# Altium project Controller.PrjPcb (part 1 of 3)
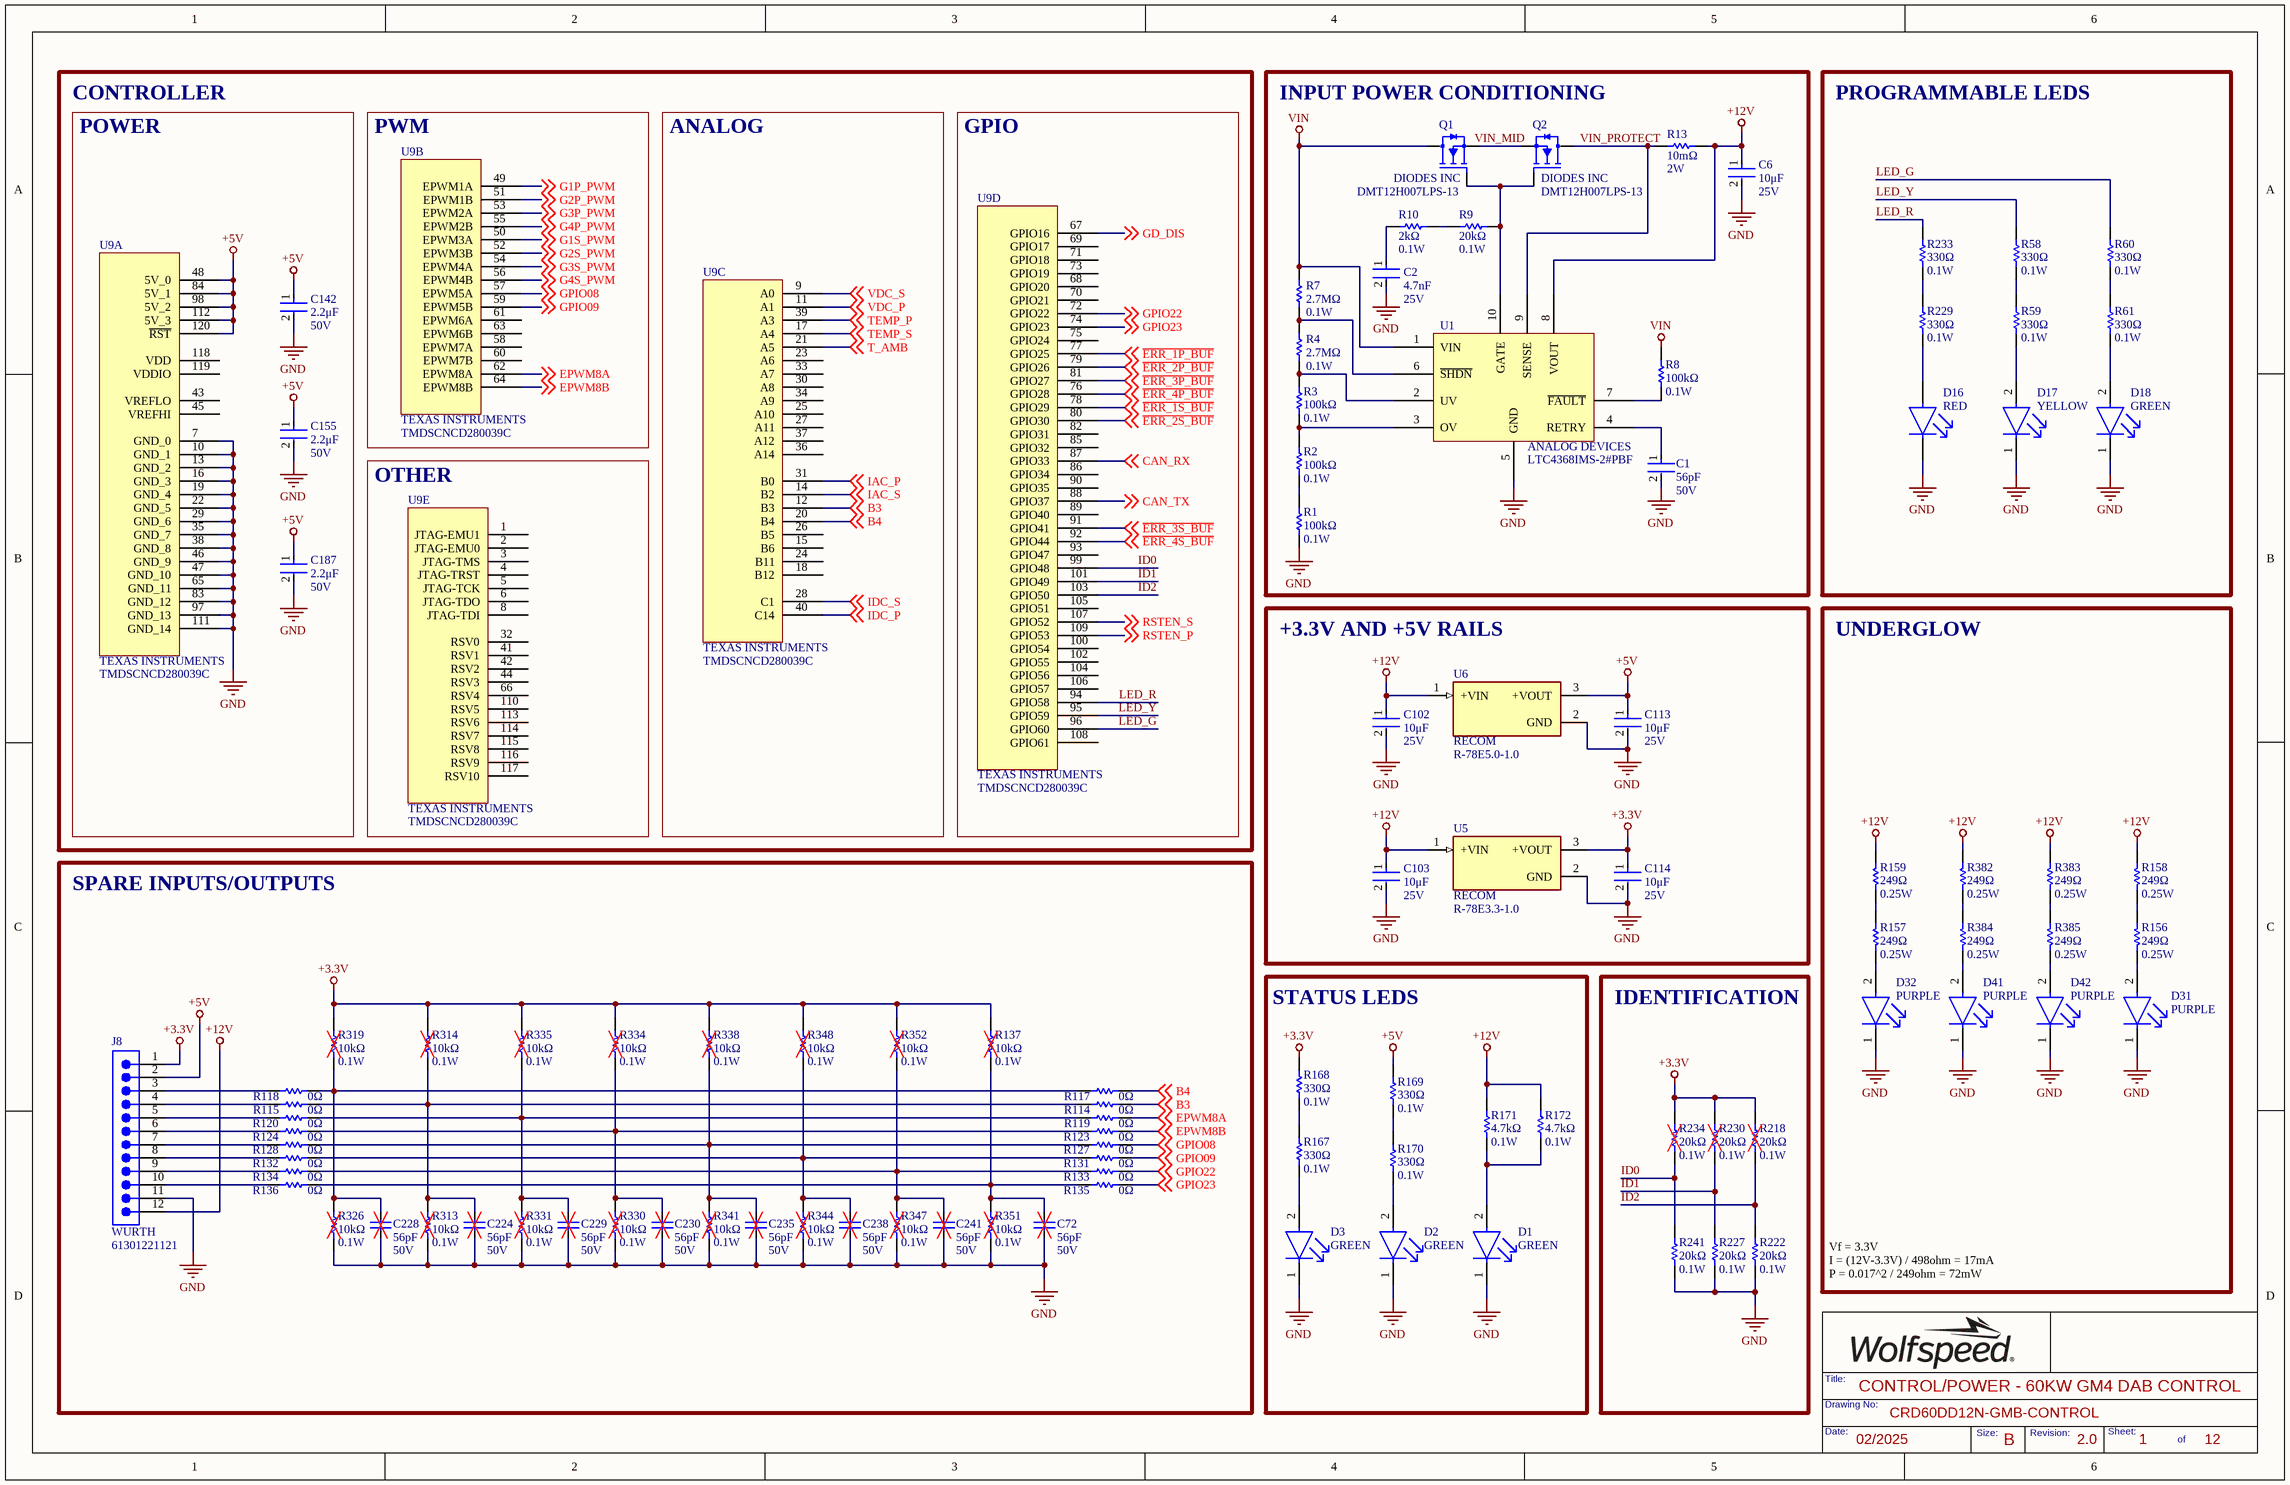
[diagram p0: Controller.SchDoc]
12 sheets, 761 parts. Net scope: global (net labels, ports and power ports of the same name join across sheets).
Board file: Controller.PcbDoc
Sheets:
  Controller.SchDoc
  Input-Output.SchDoc
  Drivers - 12P.SchDoc
  Drivers - 34P.SchDoc
  Drivers - 12S.SchDoc
  Drivers - 34S.SchDoc
  Fault Logic - P.SchDoc
  Fault Logic - S.SchDoc
  Level Shifting.SchDoc
  Voltage Sense.SchDoc
  Current Sense - P.SchDoc
  Current Sense - S.SchDoc

## Sheet Controller.SchDoc: CONTROL/POWER - 60KW GM4 DAB CONTROL
size 431 x 279 mm; Date: 02/2025; DocumentNumber: CRD60DD12N-GMB-CONTROL; Revision: 2.0; SheetNumber: 1; SheetTotal: 12; SheetSize: B

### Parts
C1  Capacitance: 56pF  Voltage Rating: 50V  [FP-C0603C-CF-IPC_B]  (hidden comment: CL10C560JB8NNNC)
C2  Voltage Rating: 25V  Capacitance: 4.7nF  [FP-C0603C-CF-IPC_B]  (hidden comment: C0603C472K3RAC7867)
C6  Voltage Rating: 25V  Capacitance: 10μF  [FP-CL31-IPC_B]  (hidden comment: CL31B106KAHSFNE)
C72  Capacitance: 56pF  Voltage Rating: 50V  [FP-C0603C-CF-IPC_B]  (hidden comment: CL10C560JB8NNNC)
C102  Voltage Rating: 25V  Capacitance: 10μF  [FP-CL31-IPC_B]  (hidden comment: CL31B106KAHSFNE)
C103  Voltage Rating: 25V  Capacitance: 10μF  [FP-CL31-IPC_B]  (hidden comment: CL31B106KAHSFNE)
C113  Voltage Rating: 25V  Capacitance: 10μF  [FP-CL31-IPC_B]  (hidden comment: CL31B106KAHSFNE)
C114  Voltage Rating: 25V  Capacitance: 10μF  [FP-CL31-IPC_B]  (hidden comment: CL31B106KAHSFNE)
C142  Voltage Rating: 50V  Capacitance: 2.2μF  [FP-C0603C-CF-IPC_B]  (hidden comment: GRT188R61H225ME13D)
C155  Voltage Rating: 50V  Capacitance: 2.2μF  [FP-C0603C-CF-IPC_B]  (hidden comment: GRT188R61H225ME13D)
C187  Voltage Rating: 50V  Capacitance: 2.2μF  [FP-C0603C-CF-IPC_B]  (hidden comment: GRT188R61H225ME13D)
C224  Capacitance: 56pF  Voltage Rating: 50V  [FP-C0603C-CF-IPC_B]  (hidden comment: CL10C560JB8NNNC)
C228  Capacitance: 56pF  Voltage Rating: 50V  [FP-C0603C-CF-IPC_B]  (hidden comment: CL10C560JB8NNNC)
C229  Capacitance: 56pF  Voltage Rating: 50V  [FP-C0603C-CF-IPC_B]  (hidden comment: CL10C560JB8NNNC)
C230  Capacitance: 56pF  Voltage Rating: 50V  [FP-C0603C-CF-IPC_B]  (hidden comment: CL10C560JB8NNNC)
C235  Capacitance: 56pF  Voltage Rating: 50V  [FP-C0603C-CF-IPC_B]  (hidden comment: CL10C560JB8NNNC)
C238  Capacitance: 56pF  Voltage Rating: 50V  [FP-C0603C-CF-IPC_B]  (hidden comment: CL10C560JB8NNNC)
C241  Capacitance: 56pF  Voltage Rating: 50V  [FP-C0603C-CF-IPC_B]  (hidden comment: CL10C560JB8NNNC)
D1  value GREEN  [FP-LTST-C171GKT-MFG]  (hidden comment: LTST-C171GKT)
D2  value GREEN  [FP-LTST-C171GKT-MFG]  (hidden comment: LTST-C171GKT)
D3  value GREEN  [FP-LTST-C171GKT-MFG]  (hidden comment: LTST-C171GKT)
D16  value RED  [FP-LTST-C171GKT-MFG-RED]  (hidden comment: HSMC-C170)
D17  value YELLOW  [FP-LTST-C171GKT-MFG-YELLOW]  (hidden comment: LTST-C171KSKT)
D18  value GREEN  [FP-LTST-C171GKT-MFG]  (hidden comment: LTST-C171GKT)
D31  Color: PURPLE  [FP-APTR3216SECK-MFG]  (hidden comment: APTR3216-VFX)
D32  Color: PURPLE  [FP-APTR3216SECK-MFG]  (hidden comment: APTR3216-VFX)
D41  Color: PURPLE  [FP-APTR3216SECK-MFG]  (hidden comment: APTR3216-VFX)
D42  Color: PURPLE  [FP-APTR3216SECK-MFG]  (hidden comment: APTR3216-VFX)
J8  Manufacturer Print: WURTH  [FP-61301221121-MFG]  (hidden comment: 61301221121)
Q1  DMT12H007LPS-13  Manufacturer: DIODES INC  [FP-PowerDI5060-8-MFG]
Q2  DMT12H007LPS-13  Manufacturer: DIODES INC  [FP-PowerDI5060-8-MFG]
R1  Resistance: 100kΩ  Power Rating: 0.1W  [FP-MCR03-IPC_B]  (hidden comment: RC0603FR-07100KL)
R2  Resistance: 100kΩ  Power Rating: 0.1W  [FP-MCR03-IPC_B]  (hidden comment: RC0603FR-07100KL)
R3  Resistance: 100kΩ  Power Rating: 0.1W  [FP-MCR03-IPC_B]  (hidden comment: RC0603FR-07100KL)
R4  Power Rating: 0.1W  Resistance: 2.7MΩ  [FP-MCR03-IPC_B]  (hidden comment: RC0603JR-072M7L)
R7  Power Rating: 0.1W  Resistance: 2.7MΩ  [FP-MCR03-IPC_B]  (hidden comment: RC0603JR-072M7L)
R8  Resistance: 100kΩ  Power Rating: 0.1W  [FP-MCR03-IPC_B]  (hidden comment: RC0603FR-07100KL)
R9  Resistance: 20kΩ  Power Rating: 0.1W  [FP-MCR03-IPC_B]  (hidden comment: CRCW060320K0FKTA)
R10  Resistance: 2kΩ  Power Rating: 0.1W  [FP-MCR03-IPC_B]  (hidden comment: RT0603DRE072KL)
R13  Resistance: 10mΩ  Max Power Dissipation: 2W  [FP-RL2512-IPC_A]  (hidden comment: PE2512FKE7W0R01L)
R58  Resistance: 330Ω  Power Rating: 0.1W  [FP-MCR03-IPC_B]  (hidden comment: RC0603FR-13330RL)
R59  Resistance: 330Ω  Power Rating: 0.1W  [FP-MCR03-IPC_B]  (hidden comment: RC0603FR-13330RL)
R60  Resistance: 330Ω  Power Rating: 0.1W  [FP-MCR03-IPC_B]  (hidden comment: RC0603FR-13330RL)
R61  Resistance: 330Ω  Power Rating: 0.1W  [FP-MCR03-IPC_B]  (hidden comment: RC0603FR-13330RL)
R114  Resistance: 0Ω  [FP-MCR03-IPC_B]  (hidden comment: CRCW06030000Z0EB)
R115  Resistance: 0Ω  [FP-MCR03-IPC_B]  (hidden comment: CRCW06030000Z0EB)
R117  Resistance: 0Ω  [FP-MCR03-IPC_B]  (hidden comment: CRCW06030000Z0EB)
R118  Resistance: 0Ω  [FP-MCR03-IPC_B]  (hidden comment: CRCW06030000Z0EB)
R119  Resistance: 0Ω  [FP-MCR03-IPC_B]  (hidden comment: CRCW06030000Z0EB)
R120  Resistance: 0Ω  [FP-MCR03-IPC_B]  (hidden comment: CRCW06030000Z0EB)
R123  Resistance: 0Ω  [FP-MCR03-IPC_B]  (hidden comment: CRCW06030000Z0EB)
R124  Resistance: 0Ω  [FP-MCR03-IPC_B]  (hidden comment: CRCW06030000Z0EB)
R127  Resistance: 0Ω  [FP-MCR03-IPC_B]  (hidden comment: CRCW06030000Z0EB)
R128  Resistance: 0Ω  [FP-MCR03-IPC_B]  (hidden comment: CRCW06030000Z0EB)
R131  Resistance: 0Ω  [FP-MCR03-IPC_B]  (hidden comment: CRCW06030000Z0EB)
R132  Resistance: 0Ω  [FP-MCR03-IPC_B]  (hidden comment: CRCW06030000Z0EB)
R133  Resistance: 0Ω  [FP-MCR03-IPC_B]  (hidden comment: CRCW06030000Z0EB)
R134  Resistance: 0Ω  [FP-MCR03-IPC_B]  (hidden comment: CRCW06030000Z0EB)
R135  Resistance: 0Ω  [FP-MCR03-IPC_B]  (hidden comment: CRCW06030000Z0EB)
R136  Resistance: 0Ω  [FP-MCR03-IPC_B]  (hidden comment: CRCW06030000Z0EB)
R137  Resistance: 10kΩ  Max Power Dissipation: 0.1W  [FP-MCR03-IPC_B]  (hidden comment: ERJ3EKF1002V)
R156  Resistance: 249Ω  Power Rating: 0.25W  [FP-MCR18-IPC_A]  (hidden comment: RC1206FR-07249RL)
R157  Resistance: 249Ω  Power Rating: 0.25W  [FP-MCR18-IPC_A]  (hidden comment: RC1206FR-07249RL)
R158  Resistance: 249Ω  Power Rating: 0.25W  [FP-MCR18-IPC_A]  (hidden comment: RC1206FR-07249RL)
R159  Resistance: 249Ω  Power Rating: 0.25W  [FP-MCR18-IPC_A]  (hidden comment: RC1206FR-07249RL)
R167  Resistance: 330Ω  Power Rating: 0.1W  [FP-MCR03-IPC_B]  (hidden comment: RC0603FR-13330RL)
R168  Resistance: 330Ω  Power Rating: 0.1W  [FP-MCR03-IPC_B]  (hidden comment: RC0603FR-13330RL)
R169  Resistance: 330Ω  Power Rating: 0.1W  [FP-MCR03-IPC_B]  (hidden comment: RC0603FR-13330RL)
R170  Resistance: 330Ω  Power Rating: 0.1W  [FP-MCR03-IPC_B]  (hidden comment: RC0603FR-13330RL)
R171  Resistance: 4.7kΩ  Power Rating: 0.1W  [FP-MCR03-IPC_B]  (hidden comment: CRCW06034K70FKTA)
R172  Resistance: 4.7kΩ  Power Rating: 0.1W  [FP-MCR03-IPC_B]  (hidden comment: CRCW06034K70FKTA)
R218  Resistance: 20kΩ  Power Rating: 0.1W  [FP-MCR03-IPC_B]  (hidden comment: CRCW060320K0FKTA)
R222  Resistance: 20kΩ  Power Rating: 0.1W  [FP-MCR03-IPC_B]  (hidden comment: CRCW060320K0FKTA)
R227  Resistance: 20kΩ  Power Rating: 0.1W  [FP-MCR03-IPC_B]  (hidden comment: CRCW060320K0FKTA)
R229  Resistance: 330Ω  Power Rating: 0.1W  [FP-MCR03-IPC_B]  (hidden comment: RC0603FR-13330RL)
R230  Resistance: 20kΩ  Power Rating: 0.1W  [FP-MCR03-IPC_B]  (hidden comment: CRCW060320K0FKTA)
R233  Resistance: 330Ω  Power Rating: 0.1W  [FP-MCR03-IPC_B]  (hidden comment: RC0603FR-13330RL)
R234  Resistance: 20kΩ  Power Rating: 0.1W  [FP-MCR03-IPC_B]  (hidden comment: CRCW060320K0FKTA)
R241  Resistance: 20kΩ  Power Rating: 0.1W  [FP-MCR03-IPC_B]  (hidden comment: CRCW060320K0FKTA)
R313  Resistance: 10kΩ  Max Power Dissipation: 0.1W  [FP-MCR03-IPC_B]  (hidden comment: ERJ3EKF1002V)
R314  Resistance: 10kΩ  Max Power Dissipation: 0.1W  [FP-MCR03-IPC_B]  (hidden comment: ERJ3EKF1002V)
R319  Resistance: 10kΩ  Max Power Dissipation: 0.1W  [FP-MCR03-IPC_B]  (hidden comment: ERJ3EKF1002V)
R326  Resistance: 10kΩ  Max Power Dissipation: 0.1W  [FP-MCR03-IPC_B]  (hidden comment: ERJ3EKF1002V)
R330  Resistance: 10kΩ  Max Power Dissipation: 0.1W  [FP-MCR03-IPC_B]  (hidden comment: ERJ3EKF1002V)
R331  Resistance: 10kΩ  Max Power Dissipation: 0.1W  [FP-MCR03-IPC_B]  (hidden comment: ERJ3EKF1002V)
R334  Resistance: 10kΩ  Max Power Dissipation: 0.1W  [FP-MCR03-IPC_B]  (hidden comment: ERJ3EKF1002V)
R335  Resistance: 10kΩ  Max Power Dissipation: 0.1W  [FP-MCR03-IPC_B]  (hidden comment: ERJ3EKF1002V)
R338  Resistance: 10kΩ  Max Power Dissipation: 0.1W  [FP-MCR03-IPC_B]  (hidden comment: ERJ3EKF1002V)
R341  Resistance: 10kΩ  Max Power Dissipation: 0.1W  [FP-MCR03-IPC_B]  (hidden comment: ERJ3EKF1002V)
R344  Resistance: 10kΩ  Max Power Dissipation: 0.1W  [FP-MCR03-IPC_B]  (hidden comment: ERJ3EKF1002V)
R347  Resistance: 10kΩ  Max Power Dissipation: 0.1W  [FP-MCR03-IPC_B]  (hidden comment: ERJ3EKF1002V)
R348  Resistance: 10kΩ  Max Power Dissipation: 0.1W  [FP-MCR03-IPC_B]  (hidden comment: ERJ3EKF1002V)
R351  Resistance: 10kΩ  Max Power Dissipation: 0.1W  [FP-MCR03-IPC_B]  (hidden comment: ERJ3EKF1002V)
R352  Resistance: 10kΩ  Max Power Dissipation: 0.1W  [FP-MCR03-IPC_B]  (hidden comment: ERJ3EKF1002V)
R382  Resistance: 249Ω  Power Rating: 0.25W  [FP-MCR18-IPC_A]  (hidden comment: RC1206FR-07249RL)
R383  Resistance: 249Ω  Power Rating: 0.25W  [FP-MCR18-IPC_A]  (hidden comment: RC1206FR-07249RL)
R384  Resistance: 249Ω  Power Rating: 0.25W  [FP-MCR18-IPC_A]  (hidden comment: RC1206FR-07249RL)
R385  Resistance: 249Ω  Power Rating: 0.25W  [FP-MCR18-IPC_A]  (hidden comment: RC1206FR-07249RL)
U1  LTC4368IMS-2#PBF  Manufacturer: ANALOG DEVICES  [SOP50P490X110-10N]
U5  R-78E3.3-1.0  Manufacturer Print: RECOM  [CONV_R-78E3.3-1.0]
U6  R-78E5.0-1.0  Manufacturer Print: RECOM  [CONV_R-78E5.0-1.0]
U9  Manufacturer: TEXAS INSTRUMENTS  [TMDSCNCD280039C_HORZ]  (hidden comment: TMDSCNCD280039C)  (parts A,B,C,D,E of 5)

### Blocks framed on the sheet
PWM: U9
ANALOG: U9
GPIO: U9
INPUT POWER CONDITIONING: C1 C2 C6 Q1 Q2 R1-R4 R7-R10 R13 U1
PROGRAMMABLE LEDS: D16-D18 R58-R61 R229 R233
OTHER: U9
+3.3V AND +5V RAILS: C102 C103 C113 C114 U5 U6
UNDERGLOW: D31 D32 D41 D42 R156-R159 R382-R385
SPARE INPUTS/OUTPUTS: C72 C224 C228-C230 C235 C238 C241 J8 R114 R115 R117-R120 R123 R124 R127 R128 R131-R137 R313 R314 R319 R326 R330 R331 R334 R335 R338 R341 R344 R347 R348 R351 R352
STATUS LEDS: D1-D3 R167-R172
IDENTIFICATION: R218 R222 R227 R230 R234 R241

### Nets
+3.3V: C114.1 J8.1 R137.2 R168.2 R218.2 R230.2 R234.2 R314.2 R319.2 R334.2 R335.2 R338.2 R348.2 R352.2 U5.3(+VOUT)
+5V: C113.1 C142.1 C155.1 C187.1 J8.2 R169.2 U6.3(+VOUT) U9.48(5V_0) U9.84(5V_1) U9.98(5V_2) U9.112(5V_3) U9.120(~{RST})
+12V: C6.1 C102.1 C103.1 J8.12 R13.2 R158.1 R159.1 R171.2 R172.2 R382.1 R383.1 U1.8(VOUT) U5.1(+VIN) U6.1(+VIN)
GND: C1.2 C2.2 C6.2 C72.2 C102.2 C103.2 C113.2 C114.2 C142.2 C155.2 C187.2 C224.2 C228.2 C229.2 C230.2 C235.2 C238.2 C241.2 D1.1(C) D2.1(C) D3.1(C) D16.1(C) D17.1(C) D18.1(C) D31.1(C) D32.1(C) D41.1(C) D42.1(C) J8.11 R1.1 R222.1 R227.1 R241.1 R313.1 R326.1 R330.1 R331.1 R341.1 R344.1 R347.1 R351.1 U1.5(GND) U5.2(GND) U6.2(GND) U9.7(GND_0) U9.10(GND_1) U9.13(GND_2) U9.16(GND_3) U9.19(GND_4) U9.22(GND_5) U9.29(GND_6) U9.35(GND_7) U9.38(GND_8) U9.46(GND_9) U9.47(GND_10) U9.65(GND_11) U9.83(GND_12) U9.97(GND_13) U9.111(GND_14)
VIN: Q1.5(D) R7.2 R8.2 U1.1(VIN)
B3: R114.2 U9.12(B3) ; off-sheet B3
B4: R117.2 U9.20(B4) ; off-sheet B4
CAN_RX: U9.87(GPIO33) ; off-sheet CAN_RX
CAN_TX: U9.88(GPIO37) ; off-sheet CAN_TX
~{ERR_1P_BUF}: U9.77(GPIO25) ; off-sheet ~{ERR_1P_BUF}
~{ERR_1S_BUF}: U9.78(GPIO29) ; off-sheet ~{ERR_1S_BUF}
~{ERR_2P_BUF}: U9.79(GPIO26) ; off-sheet ~{ERR_2P_BUF}
~{ERR_2S_BUF}: U9.80(GPIO30) ; off-sheet ~{ERR_2S_BUF}
~{ERR_3P_BUF}: U9.81(GPIO27) ; off-sheet ~{ERR_3P_BUF}
~{ERR_3S_BUF}: U9.91(GPIO41) ; off-sheet ~{ERR_3S_BUF}
~{ERR_4P_BUF}: U9.76(GPIO28) ; off-sheet ~{ERR_4P_BUF}
~{ERR_4S_BUF}: U9.92(GPIO44) ; off-sheet ~{ERR_4S_BUF}
EPWM8A: R119.2 U9.62(EPWM8A) ; off-sheet EPWM8A
EPWM8B: R123.2 U9.64(EPWM8B) ; off-sheet EPWM8B
G1P_PWM: U9.49(EPWM1A) ; off-sheet G1P_PWM
G1S_PWM: U9.50(EPWM3A) ; off-sheet G1S_PWM
G2P_PWM: U9.51(EPWM1B) ; off-sheet G2P_PWM
G2S_PWM: U9.52(EPWM3B) ; off-sheet G2S_PWM
G3P_PWM: U9.53(EPWM2A) ; off-sheet G3P_PWM
G3S_PWM: U9.54(EPWM4A) ; off-sheet G3S_PWM
G4P_PWM: U9.55(EPWM2B) ; off-sheet G4P_PWM
G4S_PWM: U9.56(EPWM4B) ; off-sheet G4S_PWM
GD_DIS: U9.67(GPIO16) ; off-sheet GD_DIS
GPIO08: R127.2 U9.57(EPWM5A) ; off-sheet GPIO08
GPIO09: R131.2 U9.59(EPWM5B) ; off-sheet GPIO09
GPIO22: R133.2 U9.72(GPIO22) ; off-sheet GPIO22
GPIO23: R135.2 U9.74(GPIO23) ; off-sheet GPIO23
IAC_P: U9.31(B0) ; off-sheet IAC_P
IAC_S: U9.14(B2) ; off-sheet IAC_S
ID0: R234.1 R241.2 U9.99(GPIO48)
ID1: R227.2 R230.1 U9.101(GPIO49)
ID2: R218.1 R222.2 U9.103(GPIO50)
IDC_P: U9.40(C14) ; off-sheet IDC_P
IDC_S: U9.28(C1) ; off-sheet IDC_S
LED_G: R60.2 U9.96(GPIO60)
LED_R: R233.2 U9.94(GPIO58)
LED_Y: R58.2 U9.95(GPIO59)
RSTEN_P: U9.109(GPIO53) ; off-sheet RSTEN_P
RSTEN_S: U9.107(GPIO52) ; off-sheet RSTEN_S
T_AMB: U9.21(A5) ; off-sheet T_AMB
TEMP_P: U9.39(A3) ; off-sheet TEMP_P
TEMP_S: U9.17(A4) ; off-sheet TEMP_S
VDC_P: U9.11(A1) ; off-sheet VDC_P
VDC_S: U9.9(A0) ; off-sheet VDC_S
VIN_MID: Q1.1,2,3(S) Q2.1,2,3(S)
VIN_PROTECT: Q2.5(D) R13.1 U1.9(SENSE)
NetC1_1: C1.1 U1.4(RETRY)
NetC2_1: C2.1 R10.1
NetC72_1: C72.1 R135.1 R136.2 R137.1 R351.2
NetC224_1: C224.1 R114.1 R115.2 R313.2 R314.1
NetC228_1: C228.1 R117.1 R118.2 R319.1 R326.2
NetC229_1: C229.1 R119.1 R120.2 R331.2 R335.1
NetC230_1: C230.1 R123.1 R124.2 R330.2 R334.1
NetC235_1: C235.1 R127.1 R128.2 R338.1 R341.2
NetC238_1: C238.1 R131.1 R132.2 R344.2 R348.1
NetC241_1: C241.1 R133.1 R134.2 R347.2 R352.1
NetD1_2: D1.2(A) R171.1 R172.1
NetD2_2: D2.2(A) R170.1
NetD3_2: D3.2(A) R167.1
NetD16_2: D16.2(A) R229.1
NetD17_2: D17.2(A) R59.1
NetD18_2: D18.2(A) R61.1
NetD31_2: D31.2(A) R156.2
NetD32_2: D32.2(A) R157.2
NetD41_2: D41.2(A) R384.2
NetD42_2: D42.2(A) R385.2
NetJ8_3: J8.3 R118.1
NetJ8_4: J8.4 R115.1
NetJ8_5: J8.5 R120.1
NetJ8_6: J8.6 R124.1
NetJ8_7: J8.7 R128.1
NetJ8_8: J8.8 R132.1
NetJ8_9: J8.9 R134.1
NetJ8_10: J8.10 R136.1
NetQ1_4: Q1.4(G) Q2.4(G) R9.2 U1.10(GATE)
NetR1_2: R1.2 R2.1
NetR2_2: R2.2 R3.1 U1.3(OV)
NetR3_2: R3.2 R4.1 U1.2(UV)
NetR4_2: R4.2 R7.1 U1.6(~{SHDN})
NetR8_1: R8.1 U1.7(~{FAULT})
NetR9_1: R9.1 R10.2
NetR58_1: R58.1 R59.2
NetR60_1: R60.1 R61.2
NetR156_1: R156.1 R158.2
NetR157_1: R157.1 R159.2
NetR167_2: R167.2 R168.1
NetR169_1: R169.1 R170.2
NetR229_2: R229.2 R233.1
NetR382_2: R382.2 R384.1
NetR383_2: R383.2 R385.1

Not connected (* = marked no-connect by the designer): U9 1(JTAG-EMU1) 2(JTAG-EMU0) 3(JTAG-TMS) 4(JTAG-TRST) 5(JTAG-TCK) 6(JTAG-TDO) 8(JTAG-TDI) 15(B6) 18(B12) 23(A6) 24(B11) 25(A10) 26(B5) 27(A11) 30(A8) 32(RSV0) 33(A7) 34(A9) 36(A14) 37(A12) 41(RSV1) 42(RSV2) 43(VREFLO) 44(RSV3) 45(VREFHI) 58(EPWM7A) 60(EPWM7B) 61(EPWM6A) 63(EPWM6B) 66(RSV4) 68(GPIO20) 69(GPIO17) 70(GPIO21) 71(GPIO18) 73(GPIO19) 75(GPIO24) 82(GPIO31) 85(GPIO32) 86(GPIO34) 89(GPIO40) 90(GPIO35) 93(GPIO47) 100(GPIO54) 102(GPIO55) 104(GPIO56) 105(GPIO51) 106(GPIO57) 108(GPIO61) 110(RSV5) 113(RSV6) 114(RSV7) 115(RSV8) 116(RSV9) 117(RSV10) 118(VDD) 119(VDDIO)

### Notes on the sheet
- CONTROLLER
- POWER
- Vf = 3.3V
  I = (12V-3.3V) / 498ohm = 17mA
  P = 0.017^2 / 249ohm = 72mW

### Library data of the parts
C1 C72 C224 C228-C230 C235 C238 C241 = CL10C560JB8NNNC: CAP CER 56PF 50V C0G/NP0 0603; Manufacturer: SAMSUNG; Material: Ceramic; Tolerance: 5%; Dielectric: C0G; Temperature Coefficient: 30ppm/°C
C2 = C0603C472K3RAC7867: CAP CER 4700PF 25V 10% X7R 0603; Manufacturer: KEMET; Manufacturer Part Number: C0603C472K3RACTU; Dielectric Material: Ceramic; Value: 4.7nF
C6 C102 C103 C113 C114 = CMP-13271-001434-1: CAP CER 10UF 25V X7R 1206; Manufacturer: SAMSUNG; Tolerance: 10%; Value: 10μF
C142 C155 C187 = GRT188R61H225ME13D: CAP CER 2.2UF 50V X5R 0603; Manufacturer: MURATA; Tolerance: 20%; Value: 2.2μF
D1-D3 D18 = LTST-C171GKT: LED GREEN CLEAR CHIP SMD; Manufacturer: LITE-ON; Luminous Intensity: 12mcd; Lens Color: Colorless; Dominant Wavelength: 569nm; Number of LEDs: 1; Power Dissipation: 100mW; Viewing Angle: 130°; Reverse Voltage: 5V; Test Current: 10mA; Forward Voltage: 2.1V; Wavelength: 585nm; Lens Style: Diffused; Forward Current: 30mA
D16 = HSMC-C170: LED RED DIFFUSED CHIP SMD; Manufacturer: BROADCOM
D17 = LTST-C171KSKT: LED YELLOW CLEAR 0805 SMD; Manufacturer: LITE-ON; Lens Color: Colorless; Number of LEDs: 1; Reverse Voltage: 5V; Viewing Angle: 130°; Lens Style: Diffused,Colorless,Rectangular,Clear; Luminous Intensity: 50mcd; Forward Voltage: 2V; Dominant Wavelength: 587nm; Test Current: 20mA; Wavelength: 588nm; Forward Current: 30mA; Max Power Dissipation: 75mW
D31 D32 D41 D42 = APTR3216-VFX: LED PURPLE CLEAR 1206 SMD; Manufacturer: KINGBRIGHT
J8 = 61301221121: CONN HEADER VERT 12POS 2.54MM; Manufacturer: WURTH ELEKTRONIK; Number of Positions: 12; Gender: Male; Voltage Rating: 250V; Pitch: 0.1inch
Q1 Q2 = DMT12H007LPS-13: MOSFET N-CH 120V 90A PWRDI5060-8
R1-R3 R8 = RC0603FR-07100KL: RES 100K OHM 1% 1/10W 0603; Manufacturer: YAGEO; Temperature Coefficient: 100ppm/°C; Voltage Rating: 50V; Working Voltage: 75V; Max Power Dissipation: 100mW; Value: 100kΩ
R4 R7 = RC0603JR-072M7L: RES 2.7M OHM 5% 1/10W 0603; Manufacturer: YAGEO; Temperature Coefficient: 100ppm/°C; Voltage Rating: 75V; Max Power Dissipation: 100mW; Voltage Rating (DC): 50V; Value: 2.7MΩ
R9 R218 R222 R227 R230 R234 R241 = CRCW060320K0FKTA: RES SMD 20K OHM 1% 1/10W 0603; Manufacturer: VISHAY DALE; Temperature Coefficient: 100ppm/°C; Voltage Rating: 75V; Max Power Dissipation: 100mW; Value: 20kΩ
R10 = RT0603DRE072KL: RES SMD 2K OHM 0.5% 1/10W 0603; Manufacturer: YAGEO; Temperature Coefficient: 50ppm/°C; Voltage Rating: 75V; Max Power Dissipation: 100mW; Voltage Rating (DC): 50V; Value: 2kΩ
R13 = PE2512FKE7W0R01L: RES 0.01 OHM 1% 2W 2512; Manufacturer: YAGEO; Temperature Coefficient: 50ppm/°C; Value: 10mΩ
R58-R61 R167-R170 R229 R233 = RC0603FR-13330RL: RES 330 OHM 1% 1/10W 0603; Manufacturer: YAGEO; Voltage Rating: 50V; Temperature Coefficient: 100ppm/°C; Value: 330Ω
R114 R115 R117-R120 R123 R124 R127 R128 R131-R136 = CRCW06030000Z0EB: RES SMD 0 OHM JUMPER 1/10W 0603; Manufacturer: VISHAY DALE; Max Power Dissipation: 100mW; Voltage Rating: 75V; Tolerance: 1%; Temperature Coefficient: 100ppm/°C; Value: 0Ω
R137 R313 R314 R319 R326 R330 R331 R334 R335 R338 R341 R344 R347 R348 R351 R352 = ERJ3EKF1002V: RES SMD 10K OHM 1% 1/10W 0603; Manufacturer: PANASONIC; Manufacturer Part Number: ERJ-3EKF1002V; Temperature Coefficient: 100ppm/°C; Power Rating: 100mW; Voltage Rating: 75V; Value: 10kΩ
R156-R159 R382-R385 = RC1206FR-07249RL: RES 249 OHM 1% 1/4W 1206; Manufacturer: YAGEO; Voltage Rating: 200V; Temperature Coefficient: 100ppm/°C; Max Power Dissipation: 250mW; Value: 249Ω
R171 R172 = CRCW06034K70FKTA: RES SMD 4.7K OHM 1% 1/10W 0603; Manufacturer: VISHAY DALE; Voltage Rating: 75V; Max Power Dissipation: 100mW; Temperature Coefficient: 100ppm/°C; Value: 4.7kΩ
U1 = LTC4368IMS-2#PBF: IC SURGE SUPPRESSION ADJ 10MSOP
U5 = R-78E3.3-1.0: DC DC CONVERTER 3.3V 3W; Number of Outputs: 1; Min Input Voltage: 8V; Max Input Voltage: 28V; Max Output Current: 1A; Efficiency: 91%; Max Output Power: 3.3W; Min Input Voltage (DC): 7V
U6 = R-78E5.0-1.0: DC DC CONVERTER 5V 5W; Number of Outputs: 1; Min Input Voltage: 8V; Max Input Voltage: 28V; Max Output Current: 1A; Efficiency: 91%
U9 = TMDSCNCD280039C: EVAL BOARD FOR TMS320F280039C

## Sheet Input-Output.SchDoc: INPUT/OUTPUT - 60KW GM4 DAB CONTROL
size 431 x 279 mm; Date: 02/2025; DocumentNumber: CRD60DD12N-GMB-CONTROL; Revision: 2.0; SheetNumber: 2; SheetTotal: 12; SheetSize: B
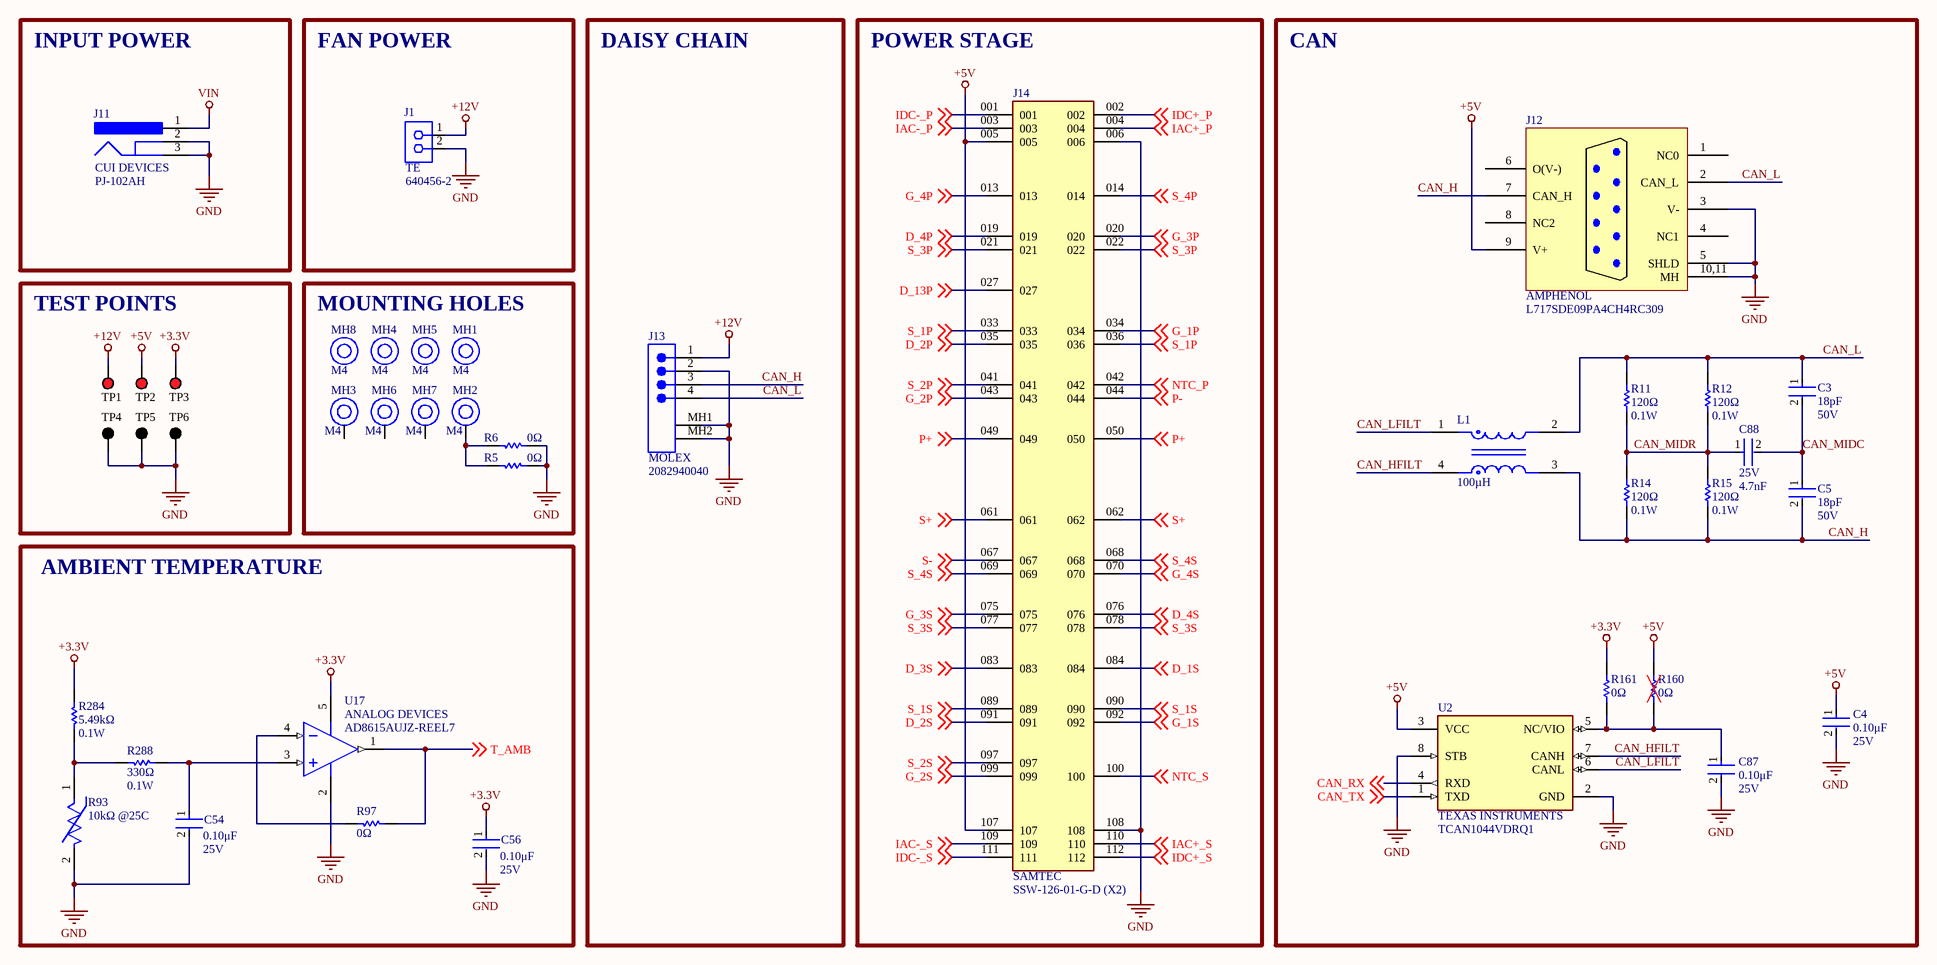
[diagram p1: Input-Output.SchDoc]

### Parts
C3  Capacitance: 18pF  Voltage Rating: 50V  [FP-C0603C-CF-IPC_B]  (hidden comment: 06035A180JAT2A)
C4  Voltage Rating: 25V  Capacitance: 0.10μF  [FP-C0603C-CF-IPC_B]  (hidden comment: C0603C104K3RACTU)
C5  Capacitance: 18pF  Voltage Rating: 50V  [FP-C0603C-CF-IPC_B]  (hidden comment: 06035A180JAT2A)
C54  Voltage Rating: 25V  Capacitance: 0.10μF  [FP-C0603C-CF-IPC_B]  (hidden comment: C0603C104K3RACTU)
C56  Voltage Rating: 25V  Capacitance: 0.10μF  [FP-C0603C-CF-IPC_B]  (hidden comment: C0603C104K3RACTU)
C87  Voltage Rating: 25V  Capacitance: 0.10μF  [FP-C0603C-CF-IPC_B]  (hidden comment: C0603C104K3RACTU)
C88  Voltage Rating: 25V  Capacitance: 4.7nF  [FP-C0603C-CF-IPC_B]  (hidden comment: C0603C472K3RAC7867)
J1  640456-2  Manufacturer: TE  [TECO-640456-2_V]
J11  PJ-102AH  Manufacturer: CUI DEVICES  [CUI-PJ-102B_V]
J12  Manufacturer: AMPHENOL  [L717SDE09PA4CH4RC309]  (hidden comment: L717SDE09PA4CH4RC309)
J13  Manufacturer: MOLEX  [2082940040]  (hidden comment: 2082940040)
J14  SSW-126-01-G-D (X2)  Manufacturer: SAMTEC  [SAMTEC_SSW-126-01-G-D_DUAL_CUSTOM]
L1  value 100µH  [FP-DLW43-0_2-t2_6-e0_6-MFG]  (hidden comment: DLW43SH101XK2L)
MH1  Size: M4  [MH_M4_NP]  (hidden comment: MH_M4_NP)
MH2  Size: M4  [MH_M4_P]  (hidden comment: MH_M4_P)
MH3  Size: M4  [MH_M4_P]  (hidden comment: MH_M4_P)
MH4  Size: M4  [MH_M4_NP]  (hidden comment: MH_M4_NP)
MH5  Size: M4  [MH_M4_NP]  (hidden comment: MH_M4_NP)
MH6  Size: M4  [MH_M4_P]  (hidden comment: MH_M4_P)
MH7  Size: M4  [MH_M4_P]  (hidden comment: MH_M4_P)
MH8  Size: M4  [MH_M4_NP]  (hidden comment: MH_M4_NP)
R5  value 0Ω  [RESC3125X70X40NL20T20]  (hidden comment: CRCW12100000Z0EAHP)
R6  value 0Ω  [RESC3125X70X40NL20T20]  (hidden comment: CRCW12100000Z0EAHP)
R11  value 120Ω  Max Power Dissipation: 0.1W  [FP-MCR03-IPC_B]  (hidden comment: RC0603JR-07120RL)
R12  value 120Ω  Max Power Dissipation: 0.1W  [FP-MCR03-IPC_B]  (hidden comment: RC0603JR-07120RL)
R14  value 120Ω  Max Power Dissipation: 0.1W  [FP-MCR03-IPC_B]  (hidden comment: RC0603JR-07120RL)
R15  value 120Ω  Max Power Dissipation: 0.1W  [FP-MCR03-IPC_B]  (hidden comment: RC0603JR-07120RL)
R93  value 10kΩ @25C  [FP-NCU18-0_15-IPC_B]  (hidden comment: NCU18XH103F6SRB)
R97  Resistance: 0Ω  [FP-MCR03-IPC_B]  (hidden comment: CRCW06030000Z0EB)
R160  Resistance: 0Ω  [FP-MCR03-IPC_B]  (hidden comment: CRCW06030000Z0EB)
R161  Resistance: 0Ω  [FP-MCR03-IPC_B]  (hidden comment: CRCW06030000Z0EB)
R284  value 5.49kΩ  Power Rating: 0.1W  [FP-MCR03-IPC_B]  (hidden comment: RC0603FR-075K49L)
R288  Resistance: 330Ω  Power Rating: 0.1W  [FP-MCR03-IPC_B]  (hidden comment: RC0603FR-13330RL)
TP1  5010  [KSTN-5010_V]  (value not drawn)
TP2  5010  [KSTN-5010_V]  (value not drawn)
TP3  5010  [KSTN-5010_V]  (value not drawn)
TP4  5011  [KSTN-5011_V]  (value not drawn)
TP5  5011  [KSTN-5011_V]  (value not drawn)
TP6  5011  [KSTN-5011_V]  (value not drawn)
U2  TCAN1044VDRQ1  Manufacturer: TEXAS INSTRUMENTS  [FP-D0008A-IPC_C]
U17  Manufacturer: ANALOG DEVICES  [ADI-UJ-5_M]  (hidden comment: AD8615AUJZ-REEL7)

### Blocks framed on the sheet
INPUT POWER: J11
FAN POWER: J1
DAISY CHAIN: J13
POWER STAGE: J14
CAN: C3-C5 C87 C88 J12 L1 R11 R12 R14 R15 R160 R161 U2
TEST POINTS: TP1-TP6
MOUNTING HOLES: MH1-MH8 R5 R6
AMBIENT TEMPERATURE: C54 C56 R93 R97 R284 R288 U17

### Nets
+3.3V: C56.1 R161.2 R284.2 TP3.1 U17.5(+V)
+5V: C4.1 J12.9(V+) J14.005 J14.107 R160.2 TP2.1 U2.3(VCC)
+12V: J1.1 J13.1 TP1.1
GND: C4.2 C54.2 C56.2 C87.2 J1.2 J11.2 J11.3 J12.3(V-) J12.5(SHLD) J12.10,11(MH) J13.2 J13.MH1 J13.MH2 J14.006 J14.108 R5.1 R6.1 R93.2 TP4.1 TP5.1 TP6.1 U2.2(GND) U2.8(STB) U17.2(-V)
VIN: J11.1
CAN_H: C5.2 J12.7(CAN_H) J13.3 L1.3 R14.1 R15.1
CAN_HFILT: L1.4 U2.7(CANH)
CAN_L: C3.1 J12.2(CAN_L) J13.4 L1.2 R11.2 R12.2
CAN_LFILT: L1.1 U2.6(CANL)
CAN_MIDC: C3.2 C5.1 C88.2
CAN_MIDR: C88.1 R11.1 R12.1 R14.2 R15.2
CAN_RX: U2.4(RXD) ; off-sheet CAN_RX
CAN_TX: U2.1(TXD) ; off-sheet CAN_TX
D_1S: J14.084 ; off-sheet D_1S
D_2P: J14.035 ; off-sheet D_2P
D_2S: J14.091 ; off-sheet D_2S
D_3S: J14.083 ; off-sheet D_3S
D_4P: J14.019 ; off-sheet D_4P
D_4S: J14.076 ; off-sheet D_4S
D_13P: J14.027 ; off-sheet D_13P
G_1P: J14.034 ; off-sheet G_1P
G_1S: J14.092 ; off-sheet G_1S
G_2P: J14.043 ; off-sheet G_2P
G_2S: J14.099 ; off-sheet G_2S
G_3P: J14.020 ; off-sheet G_3P
G_3S: J14.075 ; off-sheet G_3S
G_4P: J14.013 ; off-sheet G_4P
G_4S: J14.070 ; off-sheet G_4S
IAC+_P: J14.004 ; off-sheet IAC+_P
IAC+_S: J14.110 ; off-sheet IAC+_S
IAC-_P: J14.003 ; off-sheet IAC-_P
IAC-_S: J14.109 ; off-sheet IAC-_S
IDC+_P: J14.002 ; off-sheet IDC+_P
IDC+_S: J14.112 ; off-sheet IDC+_S
IDC-_P: J14.001 ; off-sheet IDC-_P
IDC-_S: J14.111 ; off-sheet IDC-_S
NTC_P: J14.042 ; off-sheet NTC_P
NTC_S: J14.100 ; off-sheet NTC_S
P+: J14.049 J14.050 ; off-sheet P+
P-: J14.044 ; off-sheet P-
S+: J14.061 J14.062 ; off-sheet S+
S-: J14.067 ; off-sheet S-
S_1P: J14.033 J14.036 ; off-sheet S_1P
S_1S: J14.089 J14.090 ; off-sheet S_1S
S_2P: J14.041 ; off-sheet S_2P
S_2S: J14.097 ; off-sheet S_2S
S_3P: J14.021 J14.022 ; off-sheet S_3P
S_3S: J14.077 J14.078 ; off-sheet S_3S
S_4P: J14.014 ; off-sheet S_4P
S_4S: J14.068 J14.069 ; off-sheet S_4S
T_AMB: R97.1 U17.1(OUT) ; off-sheet T_AMB
NetC54_1: C54.1 R288.2 U17.3(+IN)
NetC87_1: C87.1 R160.1 R161.1 U2.5(NC/VIO)
NetMH2_1: MH2.1 R5.2 R6.2
NetR93_1: R93.1 R284.1 R288.1
NetR97_2: R97.2 U17.4(-IN)

Not connected (* = marked no-connect by the designer): J12 1(NC0) 4(NC1) 6(O(V-)) 8(NC2); MH3 1; MH6 1; MH7 1

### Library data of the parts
C3 C5 = 06035A180JAT2A: CAP CER 18PF 50V C0G/NP0 0603; Manufacturer: KYOCERA AVX; Dielectric Material: Ceramic; Tolerance: 5%; Dielectric: C0G; Insulation Resistance: 100GR; Temperature Coefficient: 30ppm/°C
C4 C54 C56 C87 = CMP-2006-03057-2: CAP CER 0.1UF 25V X7R 0603; Manufacturer: KEMET; Value: 0.10μF; Material: Ceramic; Tolerance: 0.1; Temperature Coefficient: 30ppm/°C; Automotive Grade: Grade 1
C88 = C0603C472K3RAC7867: as C2 on sheet Controller
J1 = CMP-2000-05417-1: CONN HEADER VERT 2POS 2.54MM; Standards: RoHSCompliant,ELVCompliant,UL94V-0; Material, Housing: Polyester; Agency Approvals: CSA,UL; Brand/Series: MTA-100Series; Contact Centerline Spacing: 0.100 / in.; Material, Contact: CopperAlloy; Current, Rating: 5 / A; Color, Housing: White; Contact Termination Area Plating: Tin; Special Features: Pinstrip; Number of Positions: 2; Pin Spacing: 0.1 / "; Temperature, Operating: -55to+105 / degC; Angle: Straight; Mount Angle: Vertical; Connector Type: MTA-100; Primary Type: InterconnectSystem; Voltage, Rating: 250 / V; Mounting Hole Size: 0.04 / "
J11 = PJ-102AH: CONN PWR JACK 2X5.5MM SOLDER; Gender: Male; Shielding: Unshielded; Current Rating: 5A; Voltage Rating: 24V; Insulation Resistance: 50MR; Number of Conductors: 2
J12 = L717SDE09PA4CH4RC309: CONN D-SUB PLUG 9POS R/A SLDR; Number of Terminals/Pins: 9; Connector Type: D-Sub,Plug; Voltage Rating: 250V; Current Rating: 5A; Number of Ports: 1; Pitch: 2.74mm
J13 = 2082940040: PICO-EZMATE HC 1.8 PLUGASSY ETP
J14 = SSW-126-01-G-D_DUAL_CUSTOM: CONN RCPT 52POS 0.1 GOLD PCB (X2, MODIFIED)
L1 = CMP-006-00021-3: CMC 100UH 200MA 2LN SMD AEC-Q200; Manufacturer: MURATA
MH1 MH4 MH5 MH8 = MH_M4_NP: NYLON HEX NUT M4X07; Manufacturer: MCMASTER-CARR; Manufacturer Part Number: 93800A500
MH2 MH3 MH6 MH7 = MH_M4_P: SCREW CAP SOCKET HEAD (M4X6); Manufacturer: MCMASTER-CARR; Manufacturer Part Number: 93070A095
R5 R6 = CRCW12100000Z0EAHP: RES SMD 0 OHM JUMPER 3/4W 1210; Manufacturer: VISHAY DALE; Max Power Dissipation: 750mW
R11 R12 R14 R15 = RC0603JR-07120RL: RES SMD 120 OHM 5% 1/10W 0603; Manufacturer: YAGEO; Voltage Rating (DC): 50V; Temperature Coefficient: 100ppm/°C; Power Rating: 100mW
R93 = CMP-06022-000547-2: THERMISTOR NTC 10KOHM 3380K 0603; Manufacturer: MURATA
R97 R160 R161 = CRCW06030000Z0EB: as R114 on sheet Controller
R284 = RC0603FR-075K49L: RES 5.49K OHM 1% 1/10W 0603; Manufacturer: YAGEO; Temperature Coefficient: 100ppm/°C; Voltage Rating: 50V; Max Power Dissipation: 100mW
R288 = RC0603FR-13330RL: as R58 on sheet Controller
TP1-TP3 = CMP-1672-00002-4: PC TEST POINT MULTIPURPOSE RED; Manufacturer: KEYSTONE
TP4-TP6 = CMP-1672-00003-4: PC TEST POINT MULTIPURPOSE BLACK; Manufacturer: KEYSTONE
U2 = CMP-04872-000112-1: IC TRANSCEIVER 1/1 8SOIC
U17 = CMP-0384-02059-2: IC OPAMP GP 1 CIRCUIT TSOT23-5; Generic Part Number: AD8615; Iq/Amp: 1.7mA; V Span Max: 6V; Amplifiers Per Package: 1; Small Signal Bandwidth: 23MHz; Input Offset Voltage: 80uV; V Span Min: 2.7V; Slew Rate: 12V/us; Input Bias Current: 200fA

## Sheet Drivers - 12P.SchDoc: DRIVERS (12P) - 60KW GM4 DAB CONTROL
size 431 x 279 mm; Date: 02/2025; DocumentNumber: CRD60DD12N-GMB-CONTROL; Revision: 2.0; SheetNumber: 3; SheetTotal: 12; SheetSize: B
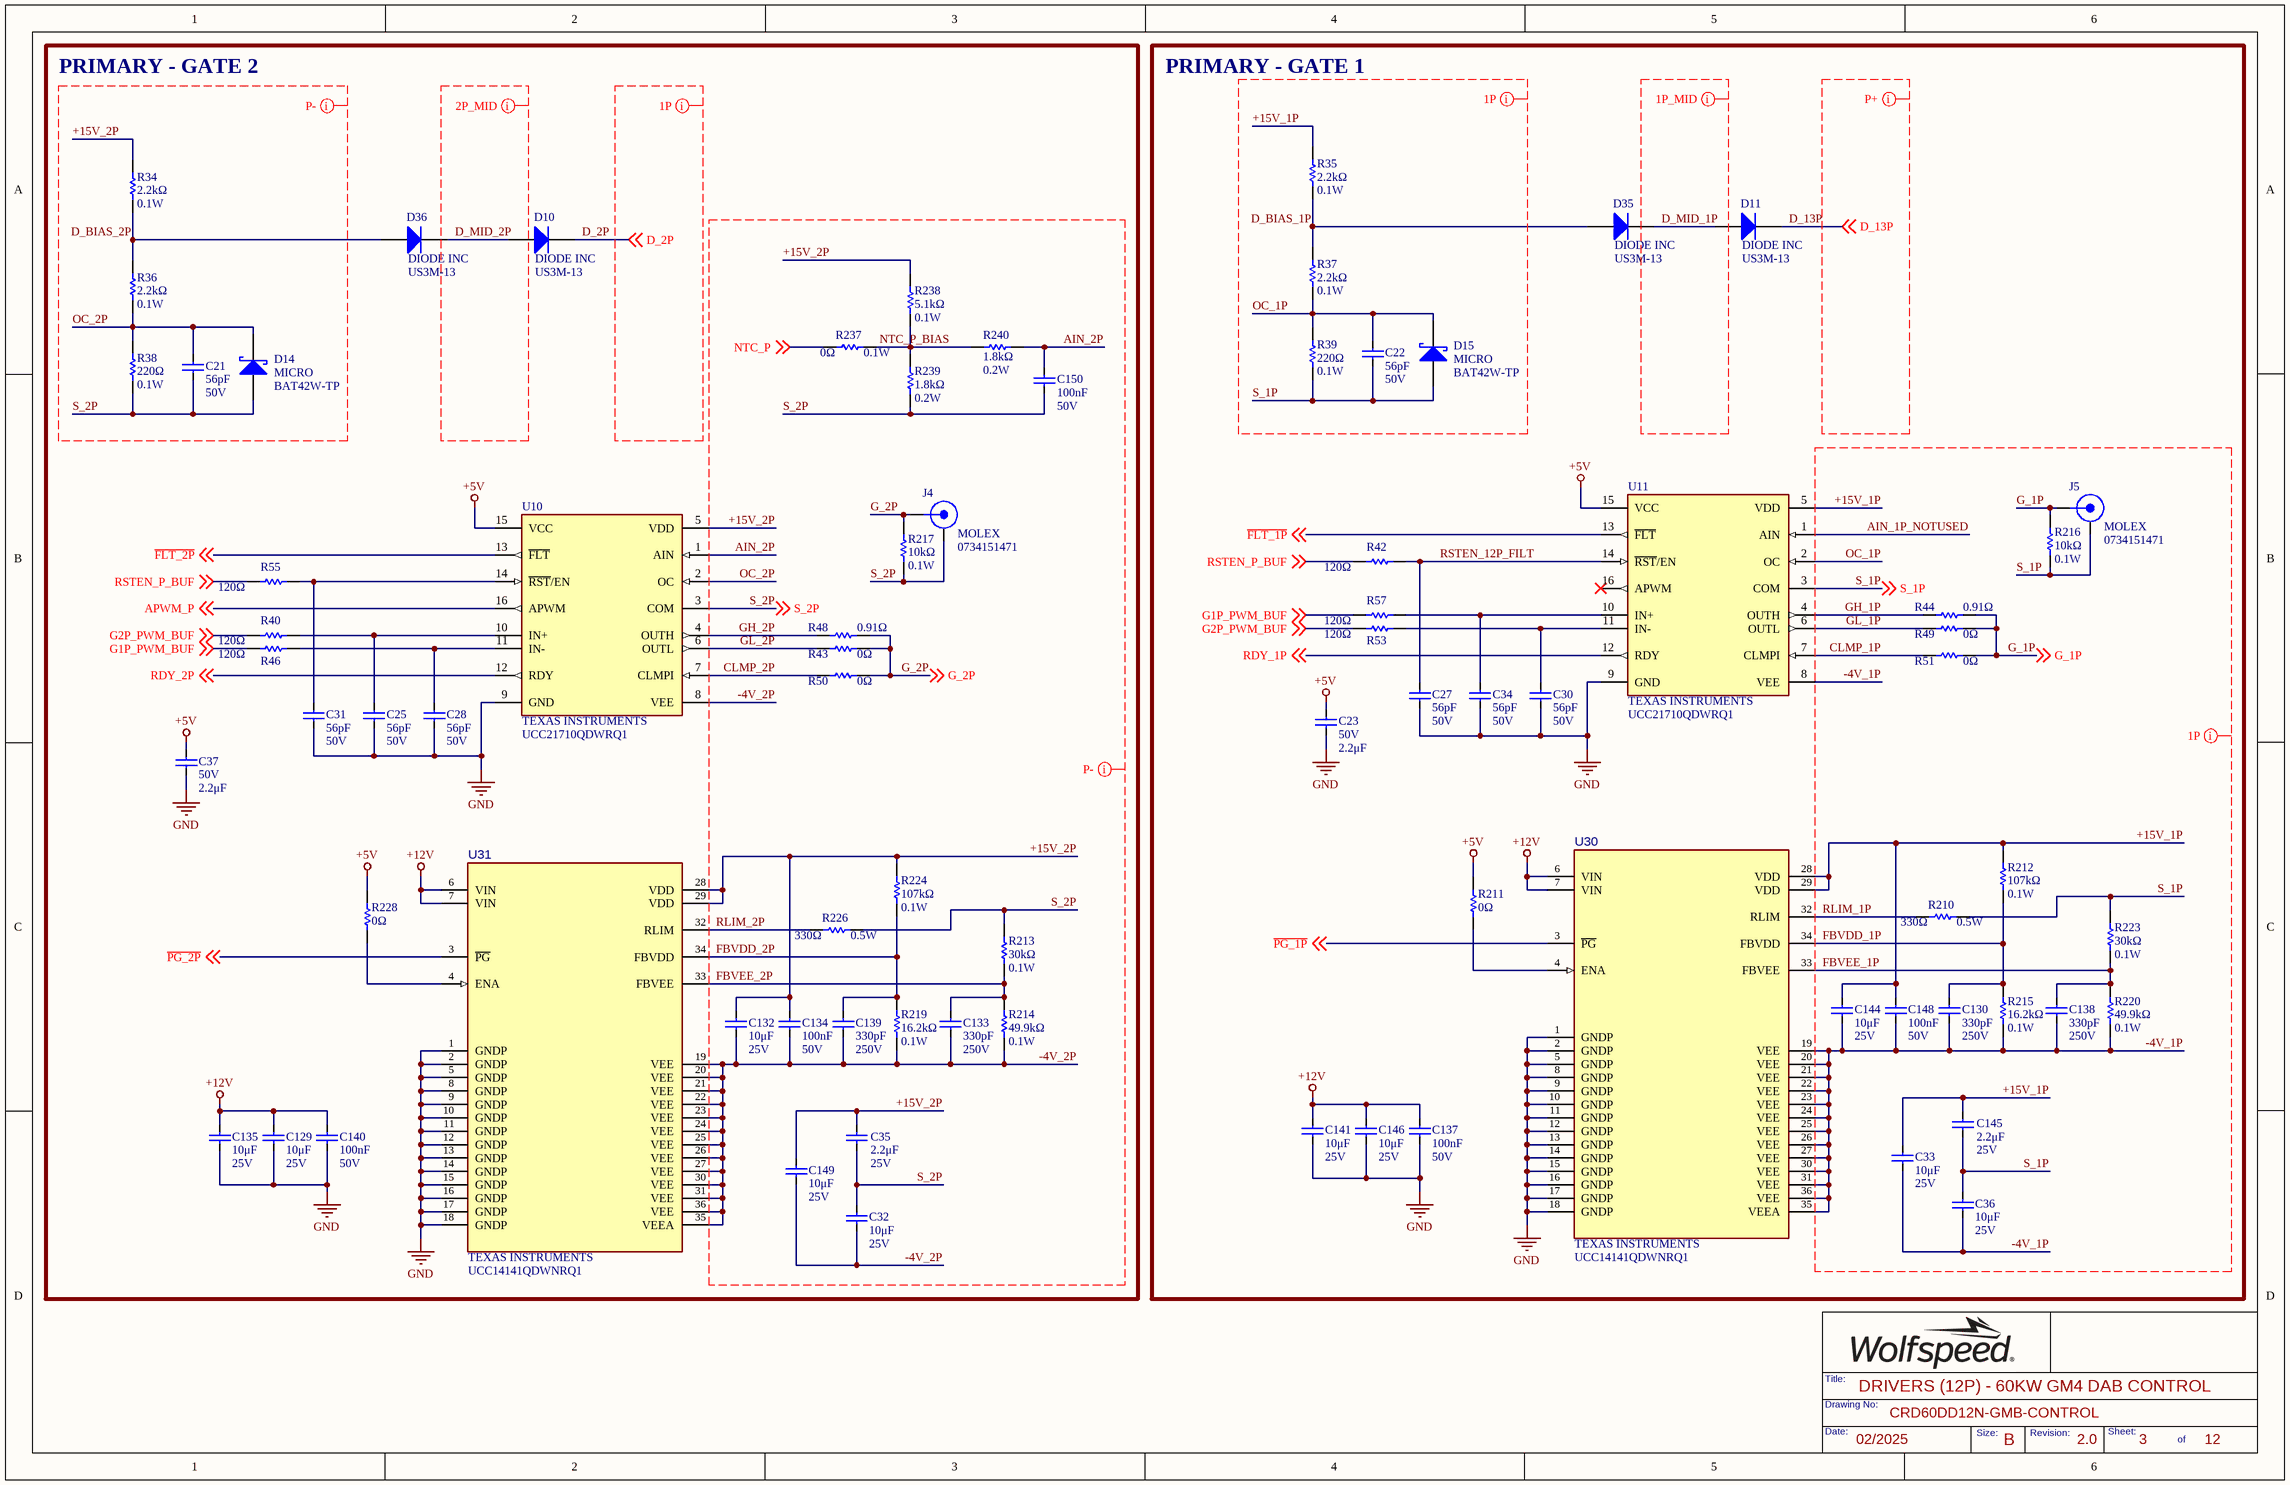
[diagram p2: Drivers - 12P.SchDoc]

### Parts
C21  Capacitance: 56pF  Voltage Rating: 50V  [FP-C0603C-CF-IPC_B]  (hidden comment: CL10C560JB8NNNC)
C22  Capacitance: 56pF  Voltage Rating: 50V  [FP-C0603C-CF-IPC_B]  (hidden comment: CL10C560JB8NNNC)
C23  Voltage Rating: 50V  Capacitance: 2.2μF  [FP-C0603C-CF-IPC_B]  (hidden comment: GRT188R61H225ME13D)
C25  Capacitance: 56pF  Voltage Rating: 50V  [FP-C0603C-CF-IPC_B]  (hidden comment: CL10C560JB8NNNC)
C27  Capacitance: 56pF  Voltage Rating: 50V  [FP-C0603C-CF-IPC_B]  (hidden comment: CL10C560JB8NNNC)
C28  Capacitance: 56pF  Voltage Rating: 50V  [FP-C0603C-CF-IPC_B]  (hidden comment: CL10C560JB8NNNC)
C30  Capacitance: 56pF  Voltage Rating: 50V  [FP-C0603C-CF-IPC_B]  (hidden comment: CL10C560JB8NNNC)
C31  Capacitance: 56pF  Voltage Rating: 50V  [FP-C0603C-CF-IPC_B]  (hidden comment: CL10C560JB8NNNC)
C32  value 10μF  Voltage Rating: 25V  [FP-CL31-IPC_C]  (hidden comment: CL31B106KAHSFNE)
C33  value 10μF  Voltage Rating: 25V  [FP-CL31-IPC_C]  (hidden comment: CL31B106KAHSFNE)
C34  Capacitance: 56pF  Voltage Rating: 50V  [FP-C0603C-CF-IPC_B]  (hidden comment: CL10C560JB8NNNC)
C35  Voltage Rating: 25V  Capacitance: 2.2μF  [FP-CL31-IPC_C]  (hidden comment: 12063C225K4T2A)
C36  value 10μF  Voltage Rating: 25V  [FP-CL31-IPC_C]  (hidden comment: CL31B106KAHSFNE)
C37  Voltage Rating: 50V  Capacitance: 2.2μF  [FP-C0603C-CF-IPC_B]  (hidden comment: GRT188R61H225ME13D)
C129  value 10μF  Voltage Rating: 25V  [FP-CL31-IPC_C]  (hidden comment: CL31B106KAHSFNE)
C130  value 330pF  Voltage Rating: 250V  [FP-C0603C-CF-IPC_B]  (hidden comment: C0603C331JAGAC7867)
C132  value 10μF  Voltage Rating: 25V  [FP-CL31-IPC_C]  (hidden comment: CL31B106KAHSFNE)
C133  value 330pF  Voltage Rating: 250V  [FP-C0603C-CF-IPC_B]  (hidden comment: C0603C331JAGAC7867)
C134  value 100nF  Voltage: 50V  [FP-C0603C-CF-IPC_B]  (hidden comment: CGA3E2X7R1H104K080AA)
C135  value 10μF  Voltage Rating: 25V  [FP-CL31-IPC_C]  (hidden comment: CL31B106KAHSFNE)
C137  value 100nF  Voltage: 50V  [FP-C0603C-CF-IPC_B]  (hidden comment: CGA3E2X7R1H104K080AA)
C138  value 330pF  Voltage Rating: 250V  [FP-C0603C-CF-IPC_B]  (hidden comment: C0603C331JAGAC7867)
C139  value 330pF  Voltage Rating: 250V  [FP-C0603C-CF-IPC_B]  (hidden comment: C0603C331JAGAC7867)
C140  value 100nF  Voltage: 50V  [FP-C0603C-CF-IPC_B]  (hidden comment: CGA3E2X7R1H104K080AA)
C141  value 10μF  Voltage Rating: 25V  [FP-CL31-IPC_C]  (hidden comment: CL31B106KAHSFNE)
C144  value 10μF  Voltage Rating: 25V  [FP-CL31-IPC_C]  (hidden comment: CL31B106KAHSFNE)
C145  Voltage Rating: 25V  Capacitance: 2.2μF  [FP-CL31-IPC_C]  (hidden comment: 12063C225K4T2A)
C146  value 10μF  Voltage Rating: 25V  [FP-CL31-IPC_C]  (hidden comment: CL31B106KAHSFNE)
C148  value 100nF  Voltage: 50V  [FP-C0603C-CF-IPC_B]  (hidden comment: CGA3E2X7R1H104K080AA)
C149  value 10μF  Voltage Rating: 25V  [FP-CL31-IPC_C]  (hidden comment: CL31B106KAHSFNE)
C150  value 100nF  Voltage: 50V  [FP-C0603C-CF-IPC_B]  (hidden comment: CGA3E2X7R1H104K080AA)
D10  Manufacturer: DIODE INC  [DIOM6959X25N]  (hidden comment: US3M-13)
D11  Manufacturer: DIODE INC  [DIOM6959X25N]  (hidden comment: US3M-13)
D14  Manufacturer: MICRO  [SOD3716X135N]  (hidden comment: BAT42W-TP)
D15  Manufacturer: MICRO  [SOD3716X135N]  (hidden comment: BAT42W-TP)
D35  Manufacturer: DIODE INC  [DIOM6959X25N]  (hidden comment: US3M-13)
D36  Manufacturer: DIODE INC  [DIOM6959X25N]  (hidden comment: US3M-13)
J4  0734151471  Manufacturer Print: MOLEX  [FP-73415-1471-MFG]
J5  0734151471  Manufacturer Print: MOLEX  [FP-73415-1471-MFG]
R34  value 2.2kΩ  Power: 0.1W  [FP-MCR03-IPC_B]  (hidden comment: RC0603FR-102K2L)
R35  value 2.2kΩ  Power: 0.1W  [FP-MCR03-IPC_B]  (hidden comment: RC0603FR-102K2L)
R36  value 2.2kΩ  Power: 0.1W  [FP-MCR03-IPC_B]  (hidden comment: RC0603FR-102K2L)
R37  value 2.2kΩ  Power: 0.1W  [FP-MCR03-IPC_B]  (hidden comment: RC0603FR-102K2L)
R38  Resistance: 220Ω  Power Rating: 0.1W  [FP-MCR03-IPC_B]  (hidden comment: RT0603FRE07220RL)
R39  Resistance: 220Ω  Power Rating: 0.1W  [FP-MCR03-IPC_B]  (hidden comment: RT0603FRE07220RL)
R40  value 120Ω  [FP-MCR03-IPC_B]  (hidden comment: RC0603JR-07120RL)
R42  value 120Ω  [FP-MCR03-IPC_B]  (hidden comment: RC0603JR-07120RL)
R43  value 0Ω  [RESC3125X70X40NL20T20]  (hidden comment: CRCW12100000Z0EAHP)
R44  value 0.91Ω  [RESC3125X70X40NL20T20]  (hidden comment: RCWE1210R910FKEA)
R46  value 120Ω  [FP-MCR03-IPC_B]  (hidden comment: RC0603JR-07120RL)
R48  value 0.91Ω  [RESC3125X70X40NL20T20]  (hidden comment: RCWE1210R910FKEA)
R49  value 0Ω  [RESC3125X70X40NL20T20]  (hidden comment: CRCW12100000Z0EAHP)
R50  Resistance: 0Ω  [FP-MCR03-IPC_B]  (hidden comment: CRCW06030000Z0EB)
R51  Resistance: 0Ω  [FP-MCR03-IPC_B]  (hidden comment: CRCW06030000Z0EB)
R53  value 120Ω  [FP-MCR03-IPC_B]  (hidden comment: RC0603JR-07120RL)
R55  value 120Ω  [FP-MCR03-IPC_B]  (hidden comment: RC0603JR-07120RL)
R57  value 120Ω  [FP-MCR03-IPC_B]  (hidden comment: RC0603JR-07120RL)
R210  value 330Ω  Power: 0.5W  [RESC3125X70X40NL20T20]  (hidden comment: RC1210JR-07330RL)
R211  Resistance: 0Ω  [FP-MCR03-IPC_B]  (hidden comment: CRCW06030000Z0EB)
R212  value 107kΩ  Power Rating: 0.1W  [FP-MCR03-IPC_B]  (hidden comment: RT0603BRD07107KL)
R213  value 30kΩ  Power Rating: 0.1W  [FP-MCR03-IPC_B]  (hidden comment: RT0603DRE0730KL)
R214  value 49.9kΩ  Power Rating: 0.1W  [FP-MCR03-IPC_B]  (hidden comment: RT0603FRE0749K9L)
R215  value 16.2kΩ  Power Rating: 0.1W  [FP-MCR03-IPC_B]  (hidden comment: RT0603BRD0716K2L)
R216  Resistance: 10kΩ  Max Power Dissipation: 0.1W  [FP-MCR03-IPC_B]  (hidden comment: ERJ3EKF1002V)
R217  Resistance: 10kΩ  Max Power Dissipation: 0.1W  [FP-MCR03-IPC_B]  (hidden comment: ERJ3EKF1002V)
R219  value 16.2kΩ  Power Rating: 0.1W  [FP-MCR03-IPC_B]  (hidden comment: RT0603BRD0716K2L)
R220  value 49.9kΩ  Power Rating: 0.1W  [FP-MCR03-IPC_B]  (hidden comment: RT0603FRE0749K9L)
R223  value 30kΩ  Power Rating: 0.1W  [FP-MCR03-IPC_B]  (hidden comment: RT0603DRE0730KL)
R224  value 107kΩ  Power Rating: 0.1W  [FP-MCR03-IPC_B]  (hidden comment: RT0603BRD07107KL)
R226  value 330Ω  Power: 0.5W  [RESC3125X70X40NL20T20]  (hidden comment: RC1210JR-07330RL)
R228  Resistance: 0Ω  [FP-MCR03-IPC_B]  (hidden comment: CRCW06030000Z0EB)
R237  Resistance: 0Ω  Power Rating: 0.1W  [FP-MCR03-IPC_B]  (hidden comment: CRCW06030000Z0EB)
R238  value 5.1kΩ  Power: 0.1W  [FP-MCR03-IPC_B]  (hidden comment: RC0603FR-075K1L)
R239  Resistance: 1.8kΩ  Max Power Dissipation: 0.2W  [FP-MCR03-IPC_B]  (hidden comment: ERJ-PB3B1801V)
R240  Resistance: 1.8kΩ  Max Power Dissipation: 0.2W  [FP-MCR03-IPC_B]  (hidden comment: ERJ-PB3B1801V)
U10  UCC21710QDWRQ1  Manufacturer: TEXAS INSTRUMENTS  [FP-DW0016B-IPC_B]
U11  UCC21710QDWRQ1  Manufacturer: TEXAS INSTRUMENTS  [FP-DW0016B-IPC_B]
U30  Manufacturer: TEXAS INSTRUMENTS  [DWN0036-IPC-MFG]  (hidden comment: UCC14141QDWNRQ1)
U31  Manufacturer: TEXAS INSTRUMENTS  [DWN0036-IPC-MFG]  (hidden comment: UCC14141QDWNRQ1)

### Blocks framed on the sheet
PRIMARY - GATE 2: C21 C25 C28 C31 C32 C35 C37 C129 C132-C135 C139 C140 C149 C150 D10 D14 D36 J4 R34 R36 R38 R40 R43 R46 R48 R50 R55 R213 R214 R217 R219 R224 R226 R228 R237-R240 U10 U31
PRIMARY - GATE 1: C22 C23 C27 C30 C33 C34 C36 C130 C137 C138 C141 C144-C146 C148 D11 D15 D35 J5 R35 R37 R39 R42 R44 R49 R51 R53 R57 R210-R212 R215 R216 R220 R223 U11 U30

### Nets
+5V: C23.1 C37.1 R211.2 R228.2 U10.15(VCC) U11.15(VCC)
+12V: C129.1 C135.1 C137.1 C140.1 C141.1 C146.1 U30.6(VIN) U30.7(VIN) U31.6(VIN) U31.7(VIN)
GND: C23.2 C25.2 C27.2 C28.2 C30.2 C31.2 C34.2 C37.2 C129.2 C135.2 C137.2 C140.2 C141.2 C146.2 U10.9(GND) U11.9(GND) U30.1(GNDP) U30.2(GNDP) U30.5(GNDP) U30.8(GNDP) U30.9(GNDP) U30.10(GNDP) U30.11(GNDP) U30.12(GNDP) U30.13(GNDP) U30.14(GNDP) U30.15(GNDP) U30.16(GNDP) U30.17(GNDP) U30.18(GNDP) U31.1(GNDP) U31.2(GNDP) U31.5(GNDP) U31.8(GNDP) U31.9(GNDP) U31.10(GNDP) U31.11(GNDP) U31.12(GNDP) U31.13(GNDP) U31.14(GNDP) U31.15(GNDP) U31.16(GNDP) U31.17(GNDP) U31.18(GNDP)
+15V_1P: C33.1 C144.1 C145.1 C148.1 R35.2 R212.2 U11.5(VDD) U30.28(VDD) U30.29(VDD)
+15V_2P: C35.1 C132.1 C134.1 C149.1 R34.2 R224.2 R238.2 U10.5(VDD) U31.28(VDD) U31.29(VDD)
-4V_1P: C33.2 C36.2 C130.2 C138.2 C144.2 C148.2 R215.1 R220.1 U11.8(VEE) U30.19(VEE) U30.20(VEE) U30.21(VEE) U30.22(VEE) U30.23(VEE) U30.24(VEE) U30.25(VEE) U30.26(VEE) U30.27(VEE) U30.30(VEE) U30.31(VEE) U30.35(VEEA) U30.36(VEE)
-4V_2P: C32.2 C132.2 C133.2 C134.2 C139.2 C149.2 R214.1 R219.1 U10.8(VEE) U31.19(VEE) U31.20(VEE) U31.21(VEE) U31.22(VEE) U31.23(VEE) U31.24(VEE) U31.25(VEE) U31.26(VEE) U31.27(VEE) U31.30(VEE) U31.31(VEE) U31.35(VEEA) U31.36(VEE)
AIN_1P_NOTUSED: U11.1(AIN)
AIN_2P: C150.1 R240.1 U10.1(AIN)
APWM_P: U10.16(APWM) ; off-sheet APWM_P
CLMP_1P: R51.1 U11.7(CLMPI)
CLMP_2P: R50.1 U10.7(CLMPI)
D_2P: D10.1(K) ; off-sheet D_2P
D_13P: D11.1(K) ; off-sheet D_13P
D_BIAS_1P: D35.2(A) R35.1 R37.2
D_BIAS_2P: D36.2(A) R34.1 R36.2
D_MID_1P: D11.2(A) D35.1(K)
D_MID_2P: D10.2(A) D36.1(K)
~{FLT_1P}: U11.13(~{FLT}) ; off-sheet ~{FLT_1P}
~{FLT_2P}: U10.13(~{FLT}) ; off-sheet ~{FLT_2P}
FBVDD_1P: C130.1 R212.1 R215.2 U30.34(FBVDD)
FBVDD_2P: C139.1 R219.2 R224.1 U31.34(FBVDD)
FBVEE_1P: C138.1 R220.2 R223.1 U30.33(FBVEE)
FBVEE_2P: C133.1 R213.1 R214.2 U31.33(FBVEE)
G1P_PWM_BUF: R46.1 R57.1 ; off-sheet G1P_PWM_BUF
G2P_PWM_BUF: R40.1 R53.1 ; off-sheet G2P_PWM_BUF
G_1P: J5.1(CENTER) R44.2 R49.2 R51.2 R216.2 ; off-sheet G_1P
G_2P: J4.1(CENTER) R43.2 R48.2 R50.2 R217.2 ; off-sheet G_2P
GH_1P: R44.1 U11.4(OUTH)
GH_2P: R48.1 U10.4(OUTH)
GL_1P: R49.1 U11.6(OUTL)
GL_2P: R43.1 U10.6(OUTL)
NTC_P: R237.1 ; off-sheet NTC_P
NTC_P_BIAS: R237.2 R238.1 R239.2 R240.2
OC_1P: C22.1 D15.1(K) R37.1 R39.2 U11.2(OC)
OC_2P: C21.1 D14.1(K) R36.1 R38.2 U10.2(OC)
~{PG_1P}: U30.3(~{PG}) ; off-sheet ~{PG_1P}
~{PG_2P}: U31.3(~{PG}) ; off-sheet ~{PG_2P}
RDY_1P: U11.12(RDY) ; off-sheet RDY_1P
RDY_2P: U10.12(RDY) ; off-sheet RDY_2P
RLIM_1P: R210.1 U30.32(RLIM)
RLIM_2P: R226.1 U31.32(RLIM)
RSTEN_12P_FILT: C27.1 R42.2 U11.14(~{RST}/EN)
RSTEN_P_BUF: R42.1 R55.1 ; off-sheet RSTEN_P_BUF
S_1P: C22.2 C36.1 C145.2 D15.2(A) J5.2,3,4,5(SHIELD) R39.1 R210.2 R216.1 R223.2 U11.3(COM) ; off-sheet S_1P
S_2P: C21.2 C32.1 C35.2 C150.2 D14.2(A) J4.2,3,4,5(SHIELD) R38.1 R213.2 R217.1 R226.2 R239.1 U10.3(COM) ; off-sheet S_2P
NetC25_1: C25.1 R40.2 U10.10(IN+)
NetC28_1: C28.1 R46.2 U10.11(IN-)
NetC30_1: C30.1 R53.2 U11.11(IN-)
NetC31_1: C31.1 R55.2 U10.14(~{RST}/EN)
NetC34_1: C34.1 R57.2 U11.10(IN+)
NetR211_1: R211.1 U30.4(ENA)
NetR228_1: R228.1 U31.4(ENA)

Not connected (* = marked no-connect by the designer): U11 16(APWM)*

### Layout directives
net class 1P_CLASS: +15V_1P, -4V_1P, AIN_1P_NOTUSED, CLMP_1P, D_2P, D_BIAS_1P, FBVDD_1P, FBVEE_1P, G_1P, GH_1P, GL_1P, OC_1P, RLIM_1P, S_1P
net class P-_CLASS: +15V_2P, -4V_2P, AIN_2P, CLMP_2P, D_BIAS_2P, FBVDD_2P, FBVEE_2P, G_2P, GH_2P, GL_2P, NTC_P, NTC_P_BIAS, OC_2P, RLIM_2P, S_2P
net class P+_CLASS: D_13P
net class 2PMID_CLASS: D_MID_2P
net class 1PMID_CLASS: D_MID_1P

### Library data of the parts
C21 C22 C25 C27 C28 C30 C31 C34 = CL10C560JB8NNNC: as C1 on sheet Controller
C23 C37 = GRT188R61H225ME13D: as C142 on sheet Controller
C32 C33 C36 C129 C132 C135 C141 C144 C146 C149 = CL31B106KAHSFNE: CAP CER 10UF 25V X7R 1206; Manufacturer: SAMSUNG; Tolerance: 10%
C35 C145 = 12063C225K4T2A: CAP CER 2.2UF 25V X7R 1206; Manufacturer: KYOCERA; Tolerance: 10%; Value: 2.2μF
C130 C133 C138 C139 = C0603C331JAGAC7867: CAP CER 330PF 250V C0G/NP0 0603; Manufacturer: KEMET; Material: Ceramic; Temperature Coefficient: 30ppm/°C; Tolerance: 0.05; Automotive Grade: Grade 1; Temperature Characteristic: C0G
C134 C137 C140 C148 C150 = CGA3E2X7R1H104K080AA: CAP CER 0.1UF 50V X7R 0603; Manufacturer: TDK; Material: 4241ConductorMaterial; Tolerance: 10%
D10 D11 D35 D36 = CMP-004-00052-3: DIODE GEN PURP 1KV 3A SMC
D14 D15 = BAT42W-TP: DIODE SCHOTTKY 30V 200MA SOD123
J4 J5 = 0734151471: CONN MMCX JACK STR 50 OHM PCB; Body Material: Brass; Body Plating: Gold; Impedance: 50R; Connector Type: PCB,MMCX,Coaxial; Max Frequency: 6GHz; Gender: Female
R34-R37 = RC0603FR-102K2L: RES 2.2K OHM 1% 1/10W 0603; Manufacturer: YAGEO
R38 R39 = RT0603FRE07220RL: RES SMD 220 OHM 1% 1/10W 0603; Manufacturer: YAGEO; Temperature Coefficient: 50 ppm/°C; Tolerance: 0.01; Voltage Rating: 75V; Value: 220Ω
R40 R42 R46 R53 R55 R57 = RC0603JR-07120RL: as R11 on sheet Input-Output
R43 R49 = CRCW12100000Z0EAHP: as R5 on sheet Input-Output
R44 R48 = CMP-2005-02198-1: RES 0.91 OHM 1% 1W 1210; Manufacturer: VISHAY DALE
R50 R51 R211 R228 R237 = CRCW06030000Z0EB: as R114 on sheet Controller
R210 R226 = RC1210JR-07330RL: RES 330 OHM 5% 1/2W 1210; Manufacturer: YAGEO
R212 R224 = RT0603BRD07107KL: RES SMD 107K OHM 0.1% 1/10W 0603; Manufacturer: YAGEO; Temperature Coefficient: 25 ppm/°C; Tolerance: 0.001; Voltage Rating: 75V
R213 R223 = RT0603DRE0730KL: RES SMD 30K OHM 0.5% 1/10W 0603; Manufacturer: YAGEO; Temperature Coefficient: 50 ppm/°C; Tolerance: 0.005; Voltage Rating: 75V
R214 R220 = RT0603FRE0749K9L: RES SMD 49.9K OHM 1% 1/10W 0603; Manufacturer: YAGEO; Temperature Coefficient: 50ppm/°C; Max Power Dissipation: 100mW; Voltage Rating: 75V; Voltage Rating (DC): 50V
R215 R219 = RT0603BRD0716K2L: RES SMD 16.2K OHM 0.1% 1/10W; Manufacturer: YAGEO; Tolerance: 0.001; Voltage Rating: 75V; Temperature Coefficient: 25 ppm/°C
R216 R217 = ERJ3EKF1002V: as R137 on sheet Controller
R238 = RC0603FR-075K1L: RES 5.1K OHM 1% 1/10W 0603; Manufacturer: YAGEO
R239 R240 = ERJ-PB3B1801V: RES SMD 1.8K OHM 0.1% 1/5W 0603; Manufacturer: PANASONIC; Temperature Coefficient: 50ppm/°C; Value: 1.8kΩ
U10 U11 = CMP-00024-00019-13: DGTL ISO 5.7KV 1CH GT DVR 16SOIC
U30 U31 = UCC14141QDWNRQ1: DUAL DC DC CONVERTER 1.5W; Part Number: UCC14240DWNQ1; Max Supply Voltage: 27V; Standoff Height: 0.1mm; SizeZ_mm: 3.55mm; AEC Qualified: Yes; Output Voltage: 18-25/2.5-25V; TaMin_C: -40°C; CompType: IC; TJmax_C: +150°C; Min Supply Voltage: 21V; AEC Grade: Grade 1; Number Of Outputs: 2; Output Type: AdjustableProgrammable; TaMax_C: +125°C; AEC Category: Q200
